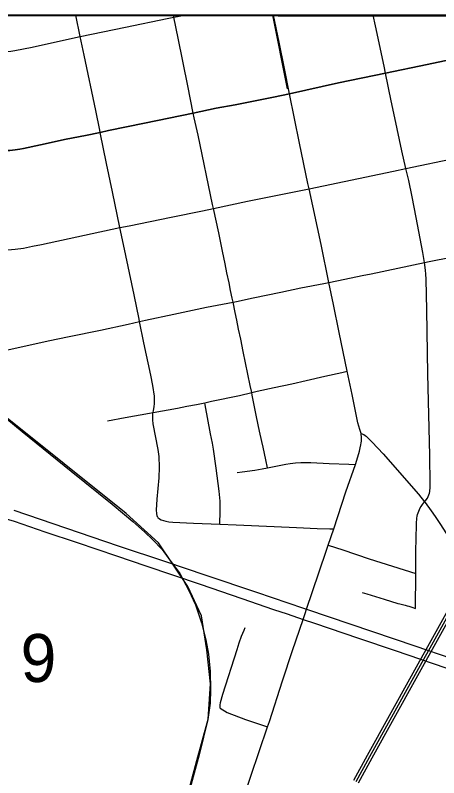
# Model space of a CAD drawing. Extents: x 0 to 34, y 0 to 22.
# Drawn here: x 8.265 to 8.634, y 20.235 to 20.9 of the extents above; entities that cross this region are included whole.
import ezdxf

# ---------------------------------------------------------------- set-up
doc = ezdxf.new("R2010")
doc.units = 0
for name, color, linetype in [('Default', 7, 'Continuous'), ('GM_X_City_Street', 7, 'Continuous'), ('GM_X_County_Road', 7, 'Continuous'), ('GM_X_Rail_Line', 7, 'Continuous'), ('GM_X_Section_Text', 7, 'Continuous'), ('GM_X_State_Route', 7, 'Continuous'), ('GM_X_US_Route', 7, 'Continuous'), ('SH_Data', 7, 'Continuous')]:
    doc.layers.add(name, color=color, linetype=linetype)

msp = doc.modelspace()

# ---------------------------------------------------------------- linework, layer by layer
at = {"layer": 'Default'}
msp.add_lwpolyline([(8.55181, 19.58508), (8.53448, 19.59436), (8.55609, 19.59502), (8.55689, 19.59709), (8.55996, 19.60597), (8.56223, 19.61505), (8.564, 19.62432), (8.56499, 19.63339), (8.56519, 19.64011), (8.5651, 19.64454), (8.5647, 19.64977), (8.56372, 19.65875), (8.56174, 19.67107), (8.80187, 19.67232), (8.80029, 19.81877), (8.86434, 19.81992), (8.86365, 19.85612), (8.9, 19.86027), (8.9, 20.89996), (7.65295, 20.89996)], dxfattribs=at)
for points in [[(7.90355, 20.89996), (7.7825, 20.89996), (7.78202, 19.88507), (8.79094, 19.88871), (8.78918, 20.89915)], [(8.78918, 20.89996), (7.90355, 20.89996), (8.78918, 20.89915)]]:
    msp.add_lwpolyline(points, close=True, dxfattribs=at)
at = {"layer": 'GM_X_City_Street'}
for points in [[(8.41986, 20.81464), (8.41514, 20.83849), (8.40666, 20.87983), (8.40298, 20.89829), (8.40265, 20.89996)], [(8.58751, 20.84941), (8.58628, 20.85539), (8.57882, 20.89075), (8.5769, 20.89996)], [(8.61371, 20.38244), (8.61399, 20.413), (8.61412, 20.43202), (8.61456, 20.45537), (8.6147, 20.45775), (8.61484, 20.45987), (8.61502, 20.4612), (8.61533, 20.46285), (8.61558, 20.46428), (8.61601, 20.46595), (8.6171, 20.46883), (8.61776, 20.47016), (8.61855, 20.47144), (8.61977, 20.47316), (8.62057, 20.47424), (8.62163, 20.47553), (8.62213, 20.47608), (8.62409, 20.47872), (8.62477, 20.48), (8.62549, 20.48157), (8.62594, 20.48297), (8.62622, 20.48448), (8.62636, 20.4854), (8.62648, 20.48737), (8.62666, 20.49096), (8.62628, 20.51575), (8.62452, 20.587), (8.62361, 20.64278), (8.62307, 20.66982), (8.62286, 20.67392), (8.62254, 20.67749), (8.62169, 20.68421), (8.6202, 20.69302), (8.61421, 20.72359), (8.6107, 20.7415), (8.60788, 20.7559), (8.60528, 20.76624), (8.60168, 20.78157), (8.59559, 20.81037), (8.59246, 20.82524), (8.58751, 20.84941)], [(8.48451, 20.50521), (8.4832, 20.51203), (8.48206, 20.51766), (8.48083, 20.52325), (8.47973, 20.52805), (8.47772, 20.53697), (8.47512, 20.54946), (8.47136, 20.56839), (8.47084, 20.57083), (8.46954, 20.57699), (8.4634, 20.60663), (8.46129, 20.6173), (8.45943, 20.62598), (8.45782, 20.63386), (8.45642, 20.64072), (8.45457, 20.64966), (8.45385, 20.65317), (8.45245, 20.6599), (8.45109, 20.66647), (8.44923, 20.67531), (8.44758, 20.68319), (8.44547, 20.69399), (8.44217, 20.70999), (8.43749, 20.73144), (8.43676, 20.7348), (8.42411, 20.79535), (8.42077, 20.81051), (8.41986, 20.81464)], [(8.12869, 20.69173), (8.13372, 20.69173), (8.14485, 20.69173), (8.19485, 20.69266), (8.25825, 20.69528), (8.2644, 20.69582), (8.27172, 20.69686), (8.27976, 20.69837), (8.28737, 20.70003), (8.35595, 20.71465)], [(8.38904, 20.46169), (8.38846, 20.46318), (8.38814, 20.46514), (8.38794, 20.46826), (8.38832, 20.47762), (8.38999, 20.49632), (8.39032, 20.5057), (8.39002, 20.51505), (8.38925, 20.52123), (8.38497, 20.54337), (8.38453, 20.5471), (8.38449, 20.54973), (8.38466, 20.55228), (8.38484, 20.55341), (8.38509, 20.55515), (8.38563, 20.55823), (8.38596, 20.56134), (8.3861, 20.56445), (8.38604, 20.56756), (8.38467, 20.57682), (8.38279, 20.58601), (8.37676, 20.61402), (8.37302, 20.6328)], [(8.34504, 20.54622), (8.36039, 20.54891), (8.38179, 20.55287), (8.38484, 20.55341), (8.40624, 20.55726), (8.4144, 20.55875), (8.42274, 20.56047), (8.4299, 20.56191), (8.43587, 20.56312), (8.46008, 20.56824), (8.47084, 20.57083), (8.47572, 20.572), (8.4905, 20.57514), (8.50593, 20.57829), (8.51849, 20.58139), (8.53476, 20.58498), (8.54959, 20.5883), (8.55417, 20.58933)], [(8.44299, 20.45592), (8.44306, 20.4575), (8.44345, 20.46581), (8.44323, 20.47587), (8.44258, 20.48462), (8.43997, 20.50492), (8.43756, 20.52146), (8.43657, 20.52649), (8.43496, 20.53471), (8.43024, 20.56011), (8.4299, 20.56191)], [(8.45817, 20.50111), (8.46249, 20.50166), (8.4737, 20.5031), (8.47997, 20.50418), (8.48451, 20.50521)], [(8.48451, 20.50521), (8.50056, 20.50821), (8.50455, 20.50885), (8.50894, 20.50931), (8.51365, 20.50961), (8.52245, 20.50965), (8.53841, 20.50901), (8.55561, 20.50825), (8.56137, 20.50798)], [(8.38904, 20.46169), (8.39044, 20.46055), (8.39194, 20.45967), (8.39396, 20.45901), (8.39606, 20.45853), (8.39848, 20.45809), (8.402, 20.45778), (8.42006, 20.45694), (8.44299, 20.45592), (8.45725, 20.45528), (8.49049, 20.45399), (8.50989, 20.45297), (8.528, 20.45228), (8.53887, 20.45194), (8.54239, 20.45184)], [(8.53767, 20.43753), (8.55024, 20.43349), (8.57328, 20.42561), (8.61399, 20.413)], [(8.56729, 20.39636), (8.57125, 20.39515), (8.58643, 20.39047), (8.59838, 20.38681), (8.60003, 20.38633), (8.60238, 20.38571), (8.60483, 20.38521), (8.60641, 20.38482), (8.60788, 20.38446), (8.61067, 20.38356), (8.61371, 20.38244)], [(8.44327, 20.2953), (8.44337, 20.29789), (8.44362, 20.30024), (8.44569, 20.30775), (8.45813, 20.34662), (8.46005, 20.35246), (8.4621, 20.35814), (8.46427, 20.36351), (8.46522, 20.36575)], [(8.44327, 20.2953), (8.44956, 20.2916), (8.46558, 20.28561), (8.47758, 20.28151), (8.48465, 20.27909)]]:
    msp.add_lwpolyline(points, dxfattribs=at)
at = {"layer": 'GM_X_County_Road'}
for p, q in [((8.32136, 20.88129), (8.31749, 20.89996)), ((8.40298, 20.89829), (8.41219, 20.89996)), ((8.32587, 20.79516), (8.33866, 20.7978)), ((8.60528, 20.76624), (8.68608, 20.78321)), ((8.53767, 20.43753), (8.54239, 20.45184))]:
    msp.add_line(p, q, dxfattribs=at)
for points in [[(8.32136, 20.88129), (8.36077, 20.88962), (8.39708, 20.89722), (8.40298, 20.89829)], [(8.50385, 20.83153), (8.49914, 20.85506), (8.49481, 20.87644), (8.48991, 20.89996)], [(8.18879, 20.86881), (8.21782, 20.86842), (8.23952, 20.86821), (8.2559, 20.86844), (8.26082, 20.86875), (8.26418, 20.86918), (8.27927, 20.87212), (8.30922, 20.87873), (8.32136, 20.88129)], [(8.33866, 20.7978), (8.33826, 20.7998), (8.33482, 20.81682), (8.32469, 20.86515), (8.32136, 20.88129)], [(8.58751, 20.84941), (8.62393, 20.85697), (8.66941, 20.86645)], [(8.50385, 20.83153), (8.54669, 20.84094), (8.58751, 20.84941)], [(8.41986, 20.81464), (8.43986, 20.81876), (8.45632, 20.82186), (8.47104, 20.82475), (8.48984, 20.82857), (8.50385, 20.83153)], [(8.5209, 20.74856), (8.51992, 20.75311), (8.51261, 20.7884), (8.50385, 20.83153)], [(8.33866, 20.7978), (8.34585, 20.79928), (8.37722, 20.80588), (8.41986, 20.81464)], [(8.35595, 20.71465), (8.34949, 20.74577), (8.34406, 20.7707), (8.33866, 20.7978)], [(8.18814, 20.78239), (8.1992, 20.78223), (8.24567, 20.78175), (8.25465, 20.78182), (8.25997, 20.78195), (8.26459, 20.78243), (8.26854, 20.78303), (8.27173, 20.78372), (8.28664, 20.78684), (8.30915, 20.7917), (8.32587, 20.79516)], [(8.5209, 20.74856), (8.59469, 20.76406), (8.60528, 20.76624)], [(8.43749, 20.73144), (8.4673, 20.73771), (8.51234, 20.74683), (8.5209, 20.74856)], [(8.53818, 20.66691), (8.53134, 20.69993), (8.5209, 20.74856)], [(8.35595, 20.71465), (8.36398, 20.71631), (8.40046, 20.72384), (8.42782, 20.72942), (8.43749, 20.73144)], [(8.37302, 20.6328), (8.37261, 20.63478), (8.36826, 20.65606), (8.35899, 20.69998), (8.35595, 20.71465)], [(8.62169, 20.68421), (8.62552, 20.685), (8.63287, 20.68649), (8.64226, 20.68841), (8.64825, 20.68963), (8.65916, 20.69187), (8.67129, 20.69437), (8.68363, 20.69691), (8.69269, 20.69891), (8.70214, 20.70099)], [(8.53818, 20.66691), (8.55219, 20.66972), (8.56718, 20.67276), (8.57514, 20.67423), (8.62169, 20.68421)], [(8.45457, 20.64966), (8.45763, 20.6503), (8.47227, 20.65337), (8.49618, 20.65844), (8.51362, 20.66208), (8.53383, 20.66605), (8.53818, 20.66691)], [(8.55417, 20.58933), (8.54724, 20.62302), (8.54216, 20.64769), (8.53818, 20.66691)], [(8.37302, 20.6328), (8.37816, 20.63398), (8.40302, 20.63924), (8.43143, 20.64528), (8.45457, 20.64966)], [(8.19643, 20.59411), (8.20437, 20.59606), (8.21479, 20.59861), (8.26608, 20.6099), (8.29331, 20.6159), (8.31151, 20.61976), (8.33886, 20.62515), (8.36304, 20.63053), (8.37302, 20.6328)], [(8.56635, 20.53505), (8.56518, 20.53854), (8.56344, 20.5444), (8.56246, 20.54877), (8.55836, 20.56893), (8.55417, 20.58933)], [(8.56137, 20.50798), (8.56341, 20.51473), (8.56475, 20.51949), (8.56517, 20.52115), (8.56549, 20.52245), (8.56616, 20.52527), (8.56643, 20.52679), (8.56649, 20.52842), (8.5666, 20.53116), (8.56635, 20.53505)], [(8.56635, 20.53505), (8.56871, 20.53413), (8.56971, 20.53344), (8.57056, 20.53275), (8.5733, 20.53014), (8.57591, 20.52753), (8.58563, 20.51727), (8.61647, 20.48215), (8.62163, 20.47553)], [(8.54239, 20.45184), (8.55306, 20.48417), (8.56137, 20.50798)], [(8.62163, 20.47553), (8.62225, 20.47474), (8.62747, 20.46745), (8.6309, 20.46265), (8.63542, 20.45579), (8.64008, 20.44825), (8.65754, 20.42058), (8.66243, 20.41313), (8.66505, 20.40922)], [(8.48465, 20.27909), (8.48626, 20.28387), (8.4977, 20.31931), (8.5065, 20.34583), (8.51571, 20.37289), (8.51749, 20.37813), (8.51874, 20.3819), (8.52935, 20.41349), (8.53651, 20.434), (8.53767, 20.43753)], [(8.44463, 20.16662), (8.4567, 20.19793), (8.46522, 20.22132), (8.47016, 20.23609), (8.48465, 20.27909)]]:
    msp.add_lwpolyline(points, dxfattribs=at)
at = {"layer": 'GM_X_Rail_Line'}
msp.add_line((8.48911, 20.89996), (8.50187, 20.83585), dxfattribs=at)
for points in [[(8.55983, 20.23245), (8.5719, 20.25435), (8.61019, 20.32368), (8.65469, 20.40354), (8.69589, 20.4775), (8.72256, 20.52635), (8.73884, 20.5603), (8.75294, 20.59313), (8.79468, 20.69213), (8.82699, 20.76694), (8.84245, 20.79786), (8.85004, 20.81128), (8.85689, 20.82095), (8.86912, 20.83841), (8.87931, 20.84983), (8.89585, 20.86811), (8.9, 20.87193)], [(8.5619, 20.23132), (8.57397, 20.25322), (8.61225, 20.32255), (8.65675, 20.4024), (8.69796, 20.47637), (8.72466, 20.52528), (8.74099, 20.55933), (8.75511, 20.59222), (8.79684, 20.69121), (8.82912, 20.76595), (8.84453, 20.79676), (8.85203, 20.81002), (8.85882, 20.8196), (8.87097, 20.83695), (8.88107, 20.84827), (8.89753, 20.86646), (8.9, 20.86873)], [(8.56396, 20.23018), (8.57603, 20.25209), (8.61432, 20.32141), (8.65881, 20.40126), (8.70002, 20.47524), (8.72676, 20.52422), (8.74314, 20.55836), (8.75728, 20.5913), (8.79901, 20.69029), (8.83126, 20.76496), (8.84661, 20.79566), (8.85403, 20.80876), (8.86075, 20.81825), (8.87282, 20.8355), (8.88283, 20.8467), (8.89921, 20.86481), (8.9, 20.86554)], [(8.37971, 20.08786), (8.42311, 20.24963), (8.43297, 20.2858), (8.43495, 20.31671), (8.43166, 20.3463), (8.42706, 20.3759), (8.41522, 20.40154), (8.38957, 20.43968), (8.36129, 20.46533), (8.20018, 20.59422), (8.17519, 20.6133), (8.16072, 20.62316), (8.13639, 20.63434), (8.10417, 20.64289), (8.04761, 20.64946), (7.80955, 20.66854), (7.79319, 20.6705)], [(8.23208, 20.56843), (8.27077, 20.53685), (8.31337, 20.50224), (8.34902, 20.47326), (8.36724, 20.45825), (8.37757, 20.44905), (8.38442, 20.44255), (8.39275, 20.4337), (8.39813, 20.42658), (8.40828, 20.41279), (8.41609, 20.39804), (8.42171, 20.38562), (8.42711, 20.37), (8.43094, 20.35494), (8.43307, 20.34259), (8.43463, 20.32739), (8.43492, 20.31163), (8.43449, 20.2997), (8.43264, 20.28549), (8.42498, 20.25467), (8.41532, 20.21945), (8.38876, 20.1206), (8.37852, 20.08145)]]:
    msp.add_lwpolyline(points, dxfattribs=at)
at = {"layer": 'GM_X_State_Route'}
msp.add_line((8.33866, 20.7978), (8.32587, 20.79516), dxfattribs=at)
for points in [[(5.77739, 16.97974), (7.8038, 16.97974), (7.79043, 17.86502), (8.29598, 17.87664), (8.8033, 17.87635), (8.79838, 18.88717), (8.9, 18.88757), (8.9, 20.89996), (5.65069, 20.89996)], [(8.66941, 20.86645), (8.62393, 20.85697), (8.58751, 20.84941)], [(8.58751, 20.84941), (8.54669, 20.84094), (8.50385, 20.83153)], [(8.50385, 20.83153), (8.48984, 20.82857), (8.47104, 20.82475), (8.45632, 20.82186), (8.43986, 20.81876), (8.41986, 20.81464)], [(8.41986, 20.81464), (8.37722, 20.80588), (8.34585, 20.79928), (8.33866, 20.7978)], [(8.32587, 20.79516), (8.30915, 20.7917), (8.28664, 20.78684), (8.27173, 20.78372), (8.26854, 20.78303), (8.26459, 20.78243), (8.25997, 20.78195), (8.25465, 20.78182), (8.24567, 20.78175), (8.1992, 20.78223), (8.18814, 20.78239)], [(8.12848, 20.48436), (8.14557, 20.48329), (8.16049, 20.48153), (8.18203, 20.4782), (8.20389, 20.47424), (8.22173, 20.47034), (8.23959, 20.46546), (8.26369, 20.45845), (8.29041, 20.44936), (8.31874, 20.43989), (8.35305, 20.42818), (8.37854, 20.41963), (8.42583, 20.40353), (8.46223, 20.39117), (8.48997, 20.3816), (8.50178, 20.37764), (8.51571, 20.37289), (8.52572, 20.36951), (8.5641, 20.35657), (8.59611, 20.34561), (8.64009, 20.33068), (8.67247, 20.31967), (8.71833, 20.30437), (8.71926, 20.30405)]]:
    msp.add_lwpolyline(points, dxfattribs=at)
at = {"layer": 'GM_X_US_Route'}
for points in [[(8.12848, 20.48436), (8.14557, 20.48329), (8.16049, 20.48153), (8.18203, 20.4782), (8.20389, 20.47424), (8.22173, 20.47034), (8.23959, 20.46546), (8.26369, 20.45845), (8.29041, 20.44936), (8.31874, 20.43989), (8.35305, 20.42818), (8.37854, 20.41963), (8.42583, 20.40353), (8.46223, 20.39117), (8.48997, 20.3816), (8.50178, 20.37764), (8.51571, 20.37289), (8.52572, 20.36951), (8.5641, 20.35657), (8.59611, 20.34561), (8.64009, 20.33068), (8.67247, 20.31967), (8.71833, 20.30437), (8.71926, 20.30405)], [(8.2634, 20.46811), (8.35446, 20.43717), (8.39566, 20.42344), (8.43092, 20.41153), (8.47505, 20.39675), (8.51618, 20.38279), (8.51874, 20.3819), (8.55727, 20.36877), (8.61307, 20.3498), (8.64533, 20.33872), (8.67167, 20.32946), (8.69745, 20.32085), (8.70697, 20.31767), (8.72281, 20.31235), (8.7319, 20.30928), (8.73932, 20.30681), (8.76939, 20.29674), (8.79583, 20.28762)]]:
    msp.add_lwpolyline(points, dxfattribs=at)
at = {"layer": 'SH_Data'}
msp.add_line((2.1, 20.89996), (8.9, 20.89996), dxfattribs=at)

# ---------------------------------------------------------------- texts
at = {"layer": 'GM_X_Section_Text'}
msp.add_text('9', height=0.04186, rotation=0.00001, dxfattribs=at).set_placement((8.26929, 20.31825))

doc.saveas('drawing.dxf')
